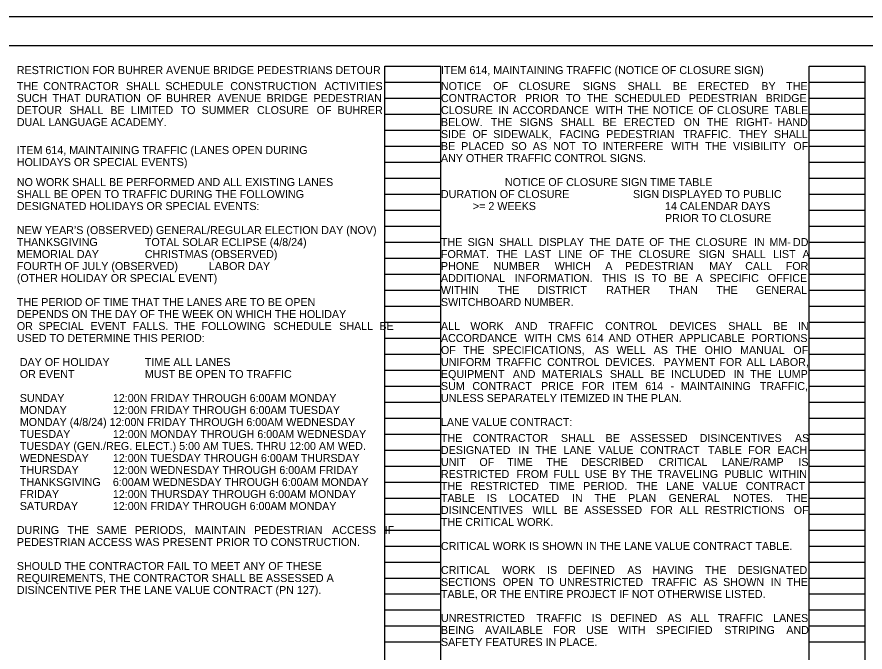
# Model space of a CAD drawing. Extents: x 0 to 43.6, y -18 to 22.
# Drawn here: x 9.82 to 24.66, y 10.88 to 22 of the extents above; entities that cross this region are included whole.
import ezdxf

# ---------------------------------------------------------------- set-up
doc = ezdxf.new("R2010")
doc.units = 0
for name, color, linetype in [('SH_Border', 7, 'Continuous'), ('SH_Cut_Line', 7, 'Continuous'), ('SH_Data', 7, 'Continuous'), ('SH_Text', 7, 'Continuous')]:
    doc.layers.add(name, color=color, linetype=linetype)

msp = doc.modelspace()

# ---------------------------------------------------------------- linework, layer by layer
at = {"layer": 'SH_Border'}
msp.add_lwpolyline([(1.5, 21.5), (33.5, 21.5), (33.5, 0.5), (1.5, 0.5)], close=True, dxfattribs=at)
at = {"layer": 'SH_Cut_Line'}
msp.add_lwpolyline([(0, 0), (34, 0), (34, 22), (0, 22)], close=True, dxfattribs=at)
at = {"layer": 'SH_Data'}
for p, q in [((16.26, 0.98), (16.26, 21.14)), ((16.26, 21.14), (17.24, 21.14)), ((17.24, 0.98), (17.24, 21.14)), ((23.68, 0.98), (23.68, 21.14)), ((23.68, 21.14), (24.66, 21.14)), ((24.66, 0.98), (24.66, 21.14)), ((16.26, 20.86), (17.24, 20.86)), ((23.68, 20.86), (24.66, 20.86)), ((16.26, 20.58), (17.24, 20.58)), ((23.68, 20.58), (24.66, 20.58)), ((16.26, 20.3), (17.24, 20.3)), ((23.68, 20.3), (24.66, 20.3)), ((16.26, 20.02), (17.24, 20.02)), ((23.68, 20.02), (24.66, 20.02)), ((16.26, 19.74), (17.24, 19.74)), ((23.68, 19.74), (24.66, 19.74)), ((16.26, 19.46), (17.24, 19.46)), ((23.68, 19.46), (24.66, 19.46)), ((16.26, 19.18), (17.24, 19.18)), ((23.68, 19.18), (24.66, 19.18)), ((16.26, 18.9), (17.24, 18.9)), ((23.68, 18.9), (24.66, 18.9)), ((16.26, 18.62), (17.24, 18.62)), ((23.68, 18.62), (24.66, 18.62)), ((16.26, 18.34), (17.24, 18.34)), ((23.68, 18.34), (24.66, 18.34)), ((16.26, 18.06), (17.24, 18.06)), ((23.68, 18.06), (24.66, 18.06)), ((16.26, 17.78), (17.24, 17.78)), ((23.68, 17.78), (24.66, 17.78)), ((16.26, 17.5), (17.24, 17.5)), ((23.68, 17.5), (24.66, 17.5)), ((16.26, 17.22), (17.24, 17.22)), ((23.68, 17.22), (24.66, 17.22)), ((16.26, 16.94), (17.24, 16.94)), ((23.68, 16.94), (24.66, 16.94)), ((16.26, 16.66), (17.24, 16.66)), ((23.68, 16.66), (24.66, 16.66)), ((16.26, 16.38), (17.24, 16.38)), ((23.68, 16.38), (24.66, 16.38)), ((16.26, 16.1), (17.24, 16.1)), ((23.68, 16.1), (24.66, 16.1)), ((16.26, 15.82), (17.24, 15.82)), ((23.68, 15.82), (24.66, 15.82)), ((16.26, 15.54), (17.24, 15.54)), ((23.68, 15.54), (24.66, 15.54)), ((16.26, 15.26), (17.24, 15.26)), ((23.68, 15.26), (24.66, 15.26)), ((16.26, 14.98), (17.24, 14.98)), ((23.68, 14.98), (24.66, 14.98)), ((16.26, 14.7), (17.24, 14.7)), ((23.68, 14.7), (24.66, 14.7)), ((16.26, 14.42), (17.24, 14.42)), ((23.68, 14.42), (24.66, 14.42)), ((16.26, 14.14), (17.24, 14.14)), ((23.68, 14.14), (24.66, 14.14)), ((16.26, 13.86), (17.24, 13.86)), ((23.68, 13.86), (24.66, 13.86)), ((16.26, 13.58), (17.24, 13.58)), ((23.68, 13.58), (24.66, 13.58)), ((16.26, 13.3), (17.24, 13.3)), ((23.68, 13.3), (24.66, 13.3)), ((16.26, 13.02), (17.24, 13.02)), ((23.68, 13.02), (24.66, 13.02)), ((16.26, 12.74), (17.24, 12.74)), ((23.68, 12.74), (24.66, 12.74)), ((16.26, 12.46), (17.24, 12.46)), ((23.68, 12.46), (24.66, 12.46)), ((16.26, 12.18), (17.24, 12.18)), ((23.68, 12.18), (24.66, 12.18)), ((16.26, 11.9), (17.24, 11.9)), ((23.68, 11.9), (24.66, 11.9)), ((16.26, 11.62), (17.24, 11.62)), ((23.68, 11.62), (24.66, 11.62)), ((16.26, 11.34), (17.24, 11.34)), ((23.68, 11.34), (24.66, 11.34)), ((16.26, 11.06), (17.24, 11.06)), ((23.68, 11.06), (24.66, 11.06))]:
    msp.add_line(p, q, dxfattribs=at)

# ---------------------------------------------------------------- texts
at = {"layer": 'SH_Text'}
for s, p in [('RESTRICTION FOR BUHRER AVENUE BRIDGE PEDESTRIANS DETOUR', (9.82, 21)), ('ITEM 614, MAINTAINING TRAFFIC (NOTICE OF CLOSURE SIGN)', (17.24, 21)), ('THE ', (9.82, 20.72)), ('CONTRACTOR ', (10.282, 20.72)), ('SHALL ', (11.73, 20.72)), ('SCHEDULE ', (12.418, 20.72)), ('CONSTRUCTION ', (13.554, 20.72)), ('ACTIVITIES ', (15.201, 20.72)), ('NOTICE ', (17.24, 20.72)), ('OF ', (18.155, 20.72)), ('CLOSURE ', (18.599, 20.72)), ('SIGNS ', (19.721, 20.72)), ('SHALL ', (20.506, 20.72)), ('BE ', (21.298, 20.72)), ('ERECTED ', (21.735, 20.72)), ('BY ', (22.846, 20.72)), ('THE ', (23.28, 20.72)), ('SUCH ', (9.82, 20.51)), ('THAT ', (10.445, 20.51)), ('DURATION ', (11.012, 20.51)), ('OF ', (12.09, 20.51)), ('BUHRER ', (12.429, 20.51)), ('AVENUE ', (13.326, 20.51)), ('BRIDGE ', (14.19, 20.51)), ('PEDESTRIAN ', (15.011, 20.51)), ('CONTRACTOR ', (17.24, 20.51)), ('PRIOR ', (18.711, 20.51)), ('TO ', (19.426, 20.51)), ('THE ', (19.789, 20.51)), ('SCHEDULED ', (20.275, 20.51)), ('PEDESTRIAN ', (21.576, 20.51)), ('BRIDGE ', (22.921, 20.51)), ('DETOUR ', (9.82, 20.3)), ('SHALL ', (10.741, 20.3)), ('BE ', (11.456, 20.3)), ('LIMITED ', (11.816, 20.3)), ('TO ', (12.686, 20.3)), ('SUMMER ', (13.053, 20.3)), ('CLOSURE ', (14.021, 20.3)), ('OF ', (15.066, 20.3)), ('BUHRER ', (15.432, 20.3)), ('CLOSURE ', (17.24, 20.3)), ('IN ', (18.243, 20.3)), ('ACCORDANCE ', (18.495, 20.3)), ('WITH ', (19.944, 20.3)), ('THE ', (20.501, 20.3)), ('NOTICE ', (20.949, 20.3)), ('OF ', (21.745, 20.3)), ('CLOSURE ', (22.07, 20.3)), ('TABLE ', (23.073, 20.3)), ('DUAL LANGUAGE ACADEMY.', (9.82, 20.09)), ('BELOW. ', (17.24, 20.09)), ('THE ', (18.113, 20.09)), ('SIGNS ', (18.617, 20.09)), ('SHALL ', (19.338, 20.09)), ('BE ', (20.066, 20.09)), ('ERECTED ', (20.44, 20.09)), ('ON ', (21.487, 20.09)), ('THE ', (21.892, 20.09)), ('RIGHT-', (22.396, 20.09)), ('HAND ', (23.128, 20.09)), ('SIDE ', (17.24, 19.88)), ('OF ', (17.792, 19.88)), ('SIDEWALK, ', (18.155, 19.88)), ('FACING ', (19.312, 19.88)), ('PEDESTRIAN ', (20.132, 19.88)), ('TRAFFIC. ', (21.477, 19.88)), ('THEY ', (22.453, 19.88)), ('SHALL ', (23.066, 19.88)), ('ITEM 614, MAINTAINING TRAFFIC (LANES OPEN DURING', (9.82, 19.6)), ('BE ', (17.24, 19.67)), ('PLACED ', (17.594, 19.67)), ('SO ', (18.471, 19.67)), ('AS ', (18.847, 19.67)), ('NOT ', (19.201, 19.67)), ('TO ', (19.707, 19.67)), ('INTERFERE ', (20.069, 19.67)), ('WITH ', (21.271, 19.67)), ('THE ', (21.864, 19.67)), ('VISIBILITY ', (22.349, 19.67)), ('OF ', (23.406, 19.67)), ('ANY OTHER TRAFFIC CONTROL SIGNS.', (17.24, 19.46)), ('HOLIDAYS OR SPECIAL EVENTS)', (9.82, 19.39)), ('NO WORK SHALL BE PERFORMED AND ALL EXISTING LANES', (9.82, 19.04)), ('NOTICE OF CLOSURE SIGN TIME TABLE', (18.36, 19.04)), ('SHALL BE OPEN TO TRAFFIC DURING THE FOLLOWING', (9.82, 18.83)), ('DURATION OF CLOSURE', (17.24, 18.83)), ('SIGN DISPLAYED TO PUBLIC', (20.6, 18.83)), ('DESIGNATED HOLIDAYS OR SPECIAL EVENTS:', (9.82, 18.62)), ('>= 2 WEEKS', (17.8, 18.62)), ('14 CALENDAR DAYS', (21.16, 18.62)), ('PRIOR TO CLOSURE', (21.16, 18.41)), ('NEW YEAR’S (OBSERVED) GENERAL/REGULAR ELECTION DAY (NOV)', (9.82, 18.2)), ('THANKSGIVING ', (9.82, 17.99)), ('TOTAL SOLAR ECLIPSE (4/8/24)', (12.06, 17.99)), ('THE ', (17.24, 17.99)), ('SIGN ', (17.707, 17.99)), ('SHALL ', (18.26, 17.99)), ('DISPLAY ', (18.952, 17.99)), ('THE ', (19.836, 17.99)), ('DATE ', (20.302, 17.99)), ('OF ', (20.885, 17.99)), ('THE ', (21.229, 17.99)), ('CLOSURE ', (21.695, 17.99)), ('IN ', (22.716, 17.99)), ('MM-', (22.987, 17.99)), ('DD ', (23.399, 17.99)), ('MEMORIAL DAY', (9.82, 17.78)), ('CHRISTMAS (OBSERVED)', (12.06, 17.78)), ('FORMAT. ', (17.24, 17.78)), ('THE ', (18.209, 17.78)), ('LAST ', (18.704, 17.78)), ('LINE ', (19.296, 17.78)), ('OF ', (19.834, 17.78)), ('THE ', (20.206, 17.78)), ('CLOSURE ', (20.7, 17.78)), ('SIGN ', (21.749, 17.78)), ('SHALL ', (22.331, 17.78)), ('LIST ', (23.05, 17.78)), ('A ', (23.567, 17.78)), ('FOURTH OF JULY (OBSERVED)', (9.82, 17.57)), ('LABOR DAY', (13.18, 17.57)), ('PHONE ', (17.24, 17.57)), ('NUMBER ', (18.159, 17.57)), ('WHICH ', (19.23, 17.57)), ('A ', (20.115, 17.57)), ('PEDESTRIAN ', (20.462, 17.57)), ('MAY ', (21.935, 17.57)), ('CALL ', (22.564, 17.57)), ('FOR ', (23.273, 17.57)), ('(OTHER HOLIDAY OR SPECIAL EVENT)', (9.82, 17.36)), ('ADDITIONAL ', (17.24, 17.36)), ('INFORMATION. ', (18.53, 17.36)), ('THIS ', (20.059, 17.36)), ('IS ', (20.624, 17.36)), ('TO ', (20.928, 17.36)), ('BE ', (21.316, 17.36)), ('A ', (21.696, 17.36)), ('SPECIFIC ', (21.939, 17.36)), ('OFFICE ', (22.961, 17.36)), ('WITHIN ', (17.24, 17.15)), ('THE ', (18.237, 17.15)), ('DISTRICT ', (18.93, 17.15)), ('RATHER ', (20.133, 17.15)), ('THAN ', (21.224, 17.15)), ('THE ', (22.058, 17.15)), ('GENERAL ', (22.751, 17.15)), ('THE PERIOD OF TIME THAT THE LANES ARE TO BE OPEN', (9.82, 16.94)), ('SWITCHBOARD NUMBER.', (17.24, 16.94)), ('DEPENDS ON THE DAY OF THE WEEK ON WHICH THE HOLIDAY', (9.82, 16.73)), ('OR ', (9.82, 16.52)), ('SPECIAL ', (10.2, 16.52)), ('EVENT ', (11.109, 16.52)), ('FALLS. ', (11.847, 16.52)), ('THE ', (12.571, 16.52)), ('FOLLOWING ', (13.049, 16.52)), ('SCHEDULE ', (14.309, 16.52)), ('SHALL ', (15.46, 16.52)), ('BE ', (16.163, 16.52)), ('ALL ', (17.24, 16.52)), ('WORK ', (17.755, 16.52)), ('AND ', (18.534, 16.52)), ('TRAFFIC ', (19.118, 16.52)), ('CONTROL ', (20.114, 16.52)), ('DEVICES ', (21.238, 16.52)), ('SHALL ', (22.267, 16.52)), ('BE ', (23.054, 16.52)), ('IN ', (23.486, 16.52)), ('USED TO DETERMINE THIS PERIOD:', (9.82, 16.31)), ('ACCORDANCE ', (17.24, 16.31)), ('WITH ', (18.701, 16.31)), ('CMS ', (19.271, 16.31)), ('614 ', (19.776, 16.31)), ('AND ', (20.172, 16.31)), ('OTHER ', (20.655, 16.31)), ('APPLICABLE ', (21.409, 16.31)), ('PORTIONS ', (22.675, 16.31)), ('OF ', (17.24, 16.1)), ('THE ', (17.628, 16.1)), ('SPECIFICATIONS, ', (18.14, 16.1)), ('AS ', (19.93, 16.1)), ('WELL ', (20.312, 16.1)), ('AS ', (20.961, 16.1)), ('THE ', (21.342, 16.1)), ('OHIO ', (21.854, 16.1)), ('MANUAL ', (22.474, 16.1)), ('OF ', (23.406, 16.1)), (' DAY OF HOLIDAY     ', (9.82, 15.89)), ('TIME ALL LANES', (12.06, 15.89)), ('UNIFORM ', (17.24, 15.89)), ('TRAFFIC ', (18.212, 15.89)), ('CONTROL ', (19.098, 15.89)), ('DEVICES.  ', (20.11, 15.89)), ('PAYMENT ', (21.137, 15.89)), ('FOR ', (22.113, 15.89)), ('ALL ', (22.586, 15.89)), ('LABOR, ', (22.99, 15.89)), (' OR EVENT', (9.82, 15.68)), ('MUST BE OPEN TO TRAFFIC', (12.06, 15.68)), ('EQUIPMENT ', (17.24, 15.68)), ('AND ', (18.498, 15.68)), ('MATERIALS ', (19.007, 15.68)), ('SHALL ', (20.197, 15.68)), ('BE ', (20.908, 15.68)), ('INCLUDED ', (21.265, 15.68)), ('IN ', (22.36, 15.68)), ('THE ', (22.651, 15.68)), ('LUMP ', (23.138, 15.68)), ('SUM ', (17.24, 15.47)), ('CONTRACT ', (17.79, 15.47)), ('PRICE ', (18.992, 15.47)), ('FOR ', (19.705, 15.47)), ('ITEM ', (20.233, 15.47)), ('614 ', (20.815, 15.47)), ('MAINTAINING ', (21.437, 15.47)), ('TRAFFIC, ', (22.82, 15.47)), ('- ', (21.257, 15.47)), (' SUNDAY     ', (9.82, 15.26)), ('12:00N FRIDAY THROUGH 6:00AM MONDAY', (11.5, 15.26)), ('UNLESS SEPARATELY ITEMIZED IN THE PLAN.', (17.24, 15.26)), (' MONDAY     ', (9.82, 15.05)), ('12:00N FRIDAY THROUGH 6:00AM TUESDAY', (11.5, 15.05)), (' MONDAY (4/8/24) 12:00N FRIDAY THROUGH 6:00AM WEDNESDAY', (9.82, 14.84)), ('LANE VALUE CONTRACT:', (17.24, 14.84)), (' TUESDAY    ', (9.82, 14.63)), ('12:00N MONDAY THROUGH 6:00AM WEDNESDAY', (11.5, 14.63)), ('THE ', (17.24, 14.56)), ('CONTRACTOR ', (17.797, 14.56)), ('SHALL ', (19.339, 14.56)), ('BE ', (20.121, 14.56)), ('ASSESSED ', (20.547, 14.56)), ('DISINCENTIVES ', (21.767, 14.56)), ('AS ', (23.433, 14.56)), (' TUESDAY (GEN./REG. ELECT.) 5:00 AM TUES. THRU 12:00 AM WED.', (9.82, 14.42)), ('DESIGNATED ', (17.24, 14.35)), ('IN ', (18.597, 14.35)), ('THE ', (18.893, 14.35)), ('LANE ', (19.384, 14.35)), ('VALUE ', (19.995, 14.35)), ('CONTRACT ', (20.725, 14.35)), ('TABLE ', (21.912, 14.35)), ('FOR ', (22.617, 14.35)), ('EACH ', (23.13, 14.35)), (' WEDNESDAY  ', (9.82, 14.21)), ('12:00N TUESDAY THROUGH 6:00AM THURSDAY', (11.5, 14.21)), ('UNIT ', (17.24, 14.14)), ('OF ', (17.913, 14.14)), ('TIME ', (18.398, 14.14)), ('THE ', (19.083, 14.14)), ('DESCRIBED ', (19.691, 14.14)), ('CRITICAL ', (21.049, 14.14)), ('LANE/RAMP ', (22.154, 14.14)), ('IS ', (23.494, 14.14)), (' THURSDAY   ', (9.82, 14)), ('12:00N WEDNESDAY THROUGH 6:00AM FRIDAY', (11.5, 14)), ('RESTRICTED ', (17.24, 13.93)), ('FROM ', (18.563, 13.93)), ('FULL ', (19.211, 13.93)), ('USE ', (19.759, 13.93)), ('BY ', (20.234, 13.93)), ('THE ', (20.564, 13.93)), ('TRAVELING ', (21.028, 13.93)), ('PUBLIC ', (22.199, 13.93)), ('WITHIN ', (22.979, 13.93)), (' THANKSGIVING', (9.82, 13.79)), ('6:00AM WEDNESDAY THROUGH 6:00AM MONDAY', (11.5, 13.79)), ('THE ', (17.24, 13.72)), ('RESTRICTED ', (17.758, 13.72)), ('TIME ', (19.135, 13.72)), ('PERIOD. ', (19.729, 13.72)), ('THE ', (20.66, 13.72)), ('LANE ', (21.178, 13.72)), ('VALUE ', (21.816, 13.72)), ('CONTRACT ', (22.574, 13.72)), (' FRIDAY     ', (9.82, 13.58)), ('12:00N THURSDAY THROUGH 6:00AM MONDAY', (11.5, 13.58)), ('IS ', (18.043, 13.51)), ('LOCATED ', (18.426, 13.51)), ('GENERAL ', (21.224, 13.51)), ('NOTES. ', (22.354, 13.51)), (' SATURDAY   ', (9.82, 13.37)), ('12:00N FRIDAY THROUGH 6:00AM MONDAY', (11.5, 13.37)), ('TABLE ', (17.24, 13.51)), ('IN ', (19.533, 13.51)), ('THE ', (19.926, 13.51)), ('PLAN ', (20.516, 13.51)), ('THE ', (23.28, 13.51)), ('DISINCENTIVES ', (17.24, 13.3)), ('WILL ', (18.839, 13.3)), ('BE ', (19.39, 13.3)), ('ASSESSED ', (19.75, 13.3)), ('FOR ', (20.903, 13.3)), ('ALL ', (21.415, 13.3)), ('RESTRICTIONS ', (21.858, 13.3)), ('OF ', (23.413, 13.3)), ('THE CRITICAL WORK.', (17.24, 13.09)), ('DURING ', (9.82, 12.95)), ('THE ', (10.707, 12.95)), ('SAME ', (11.214, 12.95)), ('PERIODS, ', (11.884, 12.95)), ('MAINTAIN ', (12.935, 12.95)), ('PEDESTRIAN ', (13.97, 12.95)), ('ACCESS ', (15.336, 12.95)), ('IF ', (16.256, 12.95)), ('PEDESTRIAN ACCESS WAS PRESENT PRIOR TO CONSTRUCTION.', (9.82, 12.74)), ('CRITICAL WORK IS SHOWN IN THE LANE VALUE CONTRACT TABLE.', (17.24, 12.67)), ('SHOULD THE CONTRACTOR FAIL TO MEET ANY OF THESE', (9.82, 12.32)), ('CRITICAL ', (17.24, 12.25)), ('WORK ', (18.308, 12.25)), ('IS ', (19.096, 12.25)), ('DEFINED ', (19.461, 12.25)), ('AS ', (20.5, 12.25)), ('HAVING ', (20.941, 12.25)), ('THE ', (21.861, 12.25)), ('DESIGNATED ', (22.432, 12.25)), ('REQUIREMENTS, THE CONTRACTOR SHALL BE ASSESSED A', (9.82, 12.11)), ('SECTIONS ', (17.24, 12.04)), ('OPEN ', (18.323, 12.04)), ('TO ', (18.959, 12.04)), ('UNRESTRICTED ', (19.31, 12.04)), ('TRAFFIC ', (20.925, 12.04)), ('AS ', (21.833, 12.04)), ('SHOWN ', (22.177, 12.04)), ('IN ', (23.009, 12.04)), ('THE ', (23.287, 12.04)), ('DISINCENTIVE PER THE LANE VALUE CONTRACT (PN 127).', (9.82, 11.9)), ('TABLE, OR THE ENTIRE PROJECT IF NOT OTHERWISE LISTED.', (17.24, 11.83)), ('UNRESTRICTED ', (17.24, 11.41)), ('TRAFFIC ', (18.912, 11.41)), ('IS ', (19.878, 11.41)), ('DEFINED ', (20.203, 11.41)), ('AS ', (21.201, 11.41)), ('ALL ', (21.602, 11.41)), ('TRAFFIC ', (22.086, 11.41)), ('LANES ', (23.052, 11.41)), ('BEING ', (17.24, 11.2)), ('AVAILABLE ', (18.01, 11.2)), ('FOR ', (19.205, 11.2)), ('USE ', (19.779, 11.2)), ('WITH ', (20.343, 11.2)), ('SPECIFIED ', (21.004, 11.2)), ('STRIPING ', (22.198, 11.2)), ('AND ', (23.283, 11.2)), ('SAFETY FEATURES IN PLACE.   ', (17.24, 10.99))]:
    msp.add_text(s, height=0.14, dxfattribs=at).set_placement(p)

doc.saveas('drawing.dxf')
